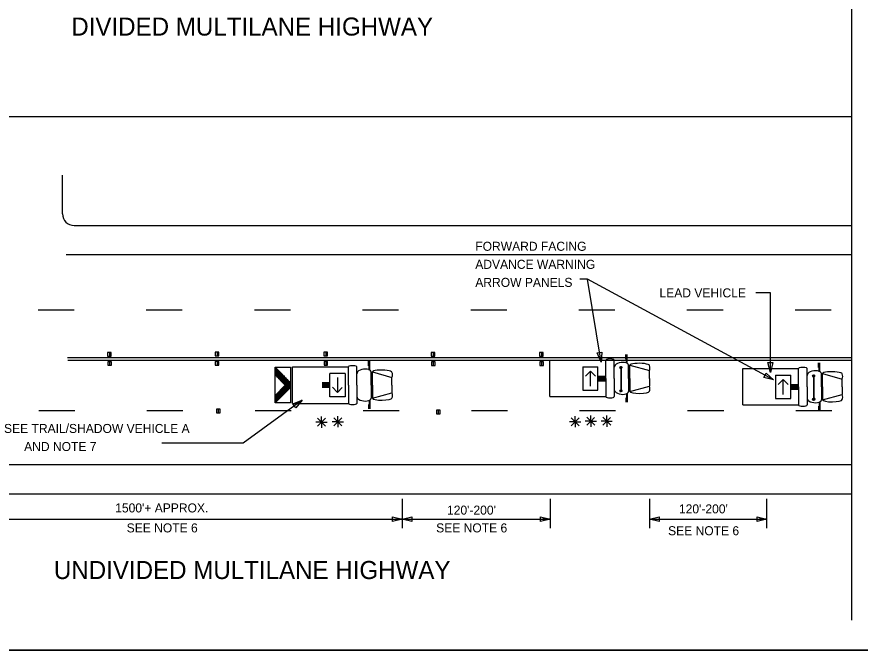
# Model space of a CAD drawing. Extents: x 1416408 to 1429341, y 372694 to 383211.
# Drawn here: x 1426733 to 1427672, y 372694 to 373399 of the extents above; entities that cross this region are included whole.
import ezdxf

# ---------------------------------------------------------------- set-up
doc = ezdxf.new("R2010")
doc.units = 0
for name, color, linetype in [('Default', 7, 'Continuous'), ('DSN_DRFT_Junk-No-Plot', 7, 'Continuous'), ('Level 1', 7, 'Continuous'), ('Working Level 1', 7, 'Continuous')]:
    doc.layers.add(name, color=color, linetype=linetype)

msp = doc.modelspace()

# ---------------------------------------------------------------- linework, layer by layer
at = {"layer": 'Default'}
for points in [[(1426234.86, 374479.9), (1426234.86, 372693.86), (1428995.11, 372693.86), (1428995.11, 374479.9)], [(1426234.86, 374479.9), (1426234.86, 372693.86), (1428995.11, 372693.86), (1428995.11, 374479.9)], [(1426234.86, 374479.9), (1428995.11, 374479.9), (1428995.11, 372693.86), (1426234.86, 372693.86)], [(1426234.86, 374479.9), (1426234.86, 372693.86), (1428995.11, 372693.86), (1428995.11, 374479.9)]]:
    msp.add_lwpolyline(points, close=True, dxfattribs=at)
at = {"layer": 'DSN_DRFT_Junk-No-Plot'}
msp.add_lwpolyline([(1426234.86, 374479.9), (1428995.11, 374479.9), (1428995.11, 372693.86), (1426234.86, 372693.86)], close=True, dxfattribs=at)
at = {"layer": 'Level 1'}
msp.add_lwpolyline([(1427050.38, 372972.19), (1426984.86, 372924.12), (1426893.95, 372924.12)], dxfattribs=at)
at = {"layer": 'Working Level 1'}
for p, q in [((1427662.56, 374447.3), (1427662.56, 372727.17)), ((1426337.99, 373287.72), (1427662, 373287.72)), ((1426783.42, 373179.42), (1426783.42, 373222.45)), ((1426796.27, 373166.43), (1427662.56, 373166.43)), ((1426787.3, 373134.22), (1427662.56, 373134.22)), ((1427575.65, 372994.53), (1427368.37, 373106.73)), ((1426788.93, 373019.55), (1427662.56, 373019.55)), ((1426833.63, 373025.14), (1426833.62, 373021.08)), ((1426833.62, 373021.08), (1426837.64, 373021.08)), ((1426837.64, 373025.14), (1426833.63, 373025.14)), ((1426835.65, 373025.14), (1426835.64, 373021.08)), ((1426837.64, 373021.08), (1426837.64, 373025.14)), ((1426953.6, 373025.45), (1426953.59, 373021.38)), ((1426953.59, 373021.38), (1426957.61, 373021.38)), ((1426957.61, 373025.45), (1426953.6, 373025.45)), ((1426955.62, 373025.45), (1426955.61, 373021.38)), ((1426957.61, 373021.38), (1426957.61, 373025.45)), ((1427074.65, 373025.31), (1427074.64, 373021.24)), ((1427074.64, 373021.24), (1427078.67, 373021.24)), ((1427078.67, 373025.31), (1427074.65, 373025.31)), ((1427076.66, 373025.31), (1427076.66, 373021.24)), ((1427078.67, 373021.24), (1427078.67, 373025.31)), ((1427194.34, 373025.08), (1427194.33, 373021.01)), ((1427194.33, 373021.01), (1427198.36, 373021.01)), ((1427198.36, 373025.08), (1427194.34, 373025.08)), ((1427196.35, 373025.08), (1427196.35, 373021.01)), ((1427198.36, 373021.01), (1427198.36, 373025.08)), ((1427314.97, 373025.08), (1427314.96, 373021.01)), ((1427314.96, 373021.01), (1427318.98, 373021.01)), ((1427318.98, 373025.08), (1427314.97, 373025.08)), ((1427316.99, 373025.08), (1427316.98, 373021.01)), ((1427318.98, 373021.01), (1427318.98, 373025.08)), ((1427411.05, 373017.86), (1427411.05, 373022.82)), ((1427411.83, 373013.07), (1427411.83, 373022.82)), ((1427412.49, 373013.07), (1427412.49, 373022.82)), ((1427476, 373019.55), (1427662.56, 373019.55)), ((1426789.49, 373016.73), (1427662.56, 373016.73)), ((1426833.81, 373014.91), (1426833.8, 373010.84)), ((1426833.8, 373010.84), (1426837.82, 373010.84)), ((1426837.82, 373014.91), (1426833.81, 373014.91)), ((1426835.83, 373014.91), (1426835.82, 373010.84)), ((1426837.82, 373010.84), (1426837.82, 373014.91)), ((1426953.65, 373015.1), (1426953.64, 373011.03)), ((1426953.64, 373011.03), (1426957.66, 373011.03)), ((1426957.66, 373015.1), (1426953.65, 373015.1)), ((1426955.66, 373015.1), (1426955.65, 373011.03)), ((1426957.66, 373011.03), (1426957.66, 373015.1)), ((1427074.83, 373014.98), (1427074.82, 373010.91)), ((1427074.82, 373010.91), (1427078.84, 373010.91)), ((1427078.84, 373014.98), (1427074.83, 373014.98)), ((1427076.85, 373014.98), (1427076.84, 373010.91)), ((1427078.84, 373010.91), (1427078.84, 373014.98)), ((1427124.25, 373010.34), (1427124.25, 373015.32)), ((1427125.02, 373005.56), (1427125.02, 373015.32)), ((1427125.68, 373005.56), (1427125.68, 373015.32)), ((1427194.52, 373014.75), (1427194.51, 373010.68)), ((1427194.51, 373010.68), (1427198.53, 373010.68)), ((1427198.53, 373014.75), (1427194.52, 373014.75)), ((1427196.54, 373014.75), (1427196.53, 373010.68)), ((1427198.53, 373010.68), (1427198.53, 373014.75)), ((1427315.15, 373014.75), (1427315.14, 373010.68)), ((1427315.14, 373010.68), (1427319.17, 373010.68)), ((1427319.17, 373014.75), (1427315.15, 373014.75)), ((1427317.16, 373014.75), (1427317.15, 373010.68)), ((1427319.17, 373010.68), (1427319.17, 373014.75)), ((1427326.51, 373016.64), (1427388.69, 373016.64)), ((1427326.51, 372976.02), (1427326.51, 373016.64)), ((1427388.69, 372996.33), (1427388.69, 373016.64)), ((1427398.21, 372996.33), (1427398.21, 373016.64)), ((1427414.17, 372996.33), (1427414.17, 373010.96)), ((1427415.5, 373010.96), (1427437.24, 373004.95)), ((1427415.5, 372996.33), (1427415.5, 373010.96)), ((1427625.84, 373008.52), (1427625.84, 373013.49)), ((1427626.62, 373003.73), (1427626.62, 373013.49)), ((1427627.28, 373003.73), (1427627.28, 373013.49)), ((1427020.31, 373008.83), (1427037.46, 372991.5)), ((1427039.69, 373009.13), (1427101.87, 373009.13)), ((1427039.69, 372968.52), (1427039.69, 373009.13)), ((1427098.23, 373001.82), (1427081.23, 373001.82)), ((1427081.23, 372975.82), (1427081.23, 373001.82)), ((1427098.23, 373001.82), (1427098.23, 372975.82)), ((1427101.87, 372988.83), (1427101.87, 373009.13)), ((1427111.4, 372988.83), (1427111.4, 373009.13)), ((1427127.36, 372988.83), (1427127.36, 373003.45)), ((1427128.68, 373003.45), (1427150.43, 372997.44)), ((1427128.68, 372988.83), (1427128.68, 373003.45)), ((1427363.03, 373009.34), (1427380.02, 373009.34)), ((1427363.03, 373009.34), (1427363.03, 372983.34)), ((1427371.53, 373004.37), (1427366.07, 372998.85)), ((1427371.53, 372987.74), (1427371.53, 373004.37)), ((1427371.53, 373004.37), (1427377.12, 372998.72)), ((1427380.02, 372983.34), (1427380.02, 373009.34)), ((1427404.28, 373008.68), (1427404.28, 373008.68)), ((1427405.3, 373008.1), (1427405.3, 372982.89)), ((1427405.37, 373008.1), (1427405.37, 372982.89)), ((1427405.45, 373008.1), (1427405.45, 372982.89)), ((1427405.58, 373008.1), (1427405.58, 372982.89)), ((1427405.74, 373009.53), (1427405.74, 373009.53)), ((1427405.77, 373008.1), (1427405.77, 372982.89)), ((1427437.24, 372996.33), (1427437.24, 373004.95)), ((1427541.29, 373007.3), (1427603.47, 373007.3)), ((1427541.29, 372966.69), (1427541.29, 373007.3)), ((1427603.47, 372987), (1427603.47, 373007.3)), ((1427613, 372987), (1427613, 373007.3)), ((1427628.96, 372987), (1427628.96, 373001.62)), ((1427630.29, 373001.62), (1427652.03, 372995.61)), ((1427630.29, 372987), (1427630.29, 373001.62)), ((1427020.31, 373000.16), (1427031.63, 372988.77)), ((1427081.23, 372991.41), (1427072.57, 372991.41)), ((1427089.73, 372997.41), (1427089.73, 372980.77)), ((1427150.43, 372988.83), (1427150.43, 372997.44)), ((1427380.02, 372998.93), (1427388.69, 372998.93)), ((1427380.02, 372997.63), (1427388.69, 372997.63)), ((1427380.02, 372996.33), (1427388.69, 372996.33)), ((1427380.02, 372995.04), (1427388.69, 372995.04)), ((1427380.02, 372993.74), (1427388.69, 372993.74)), ((1427388.69, 372996.33), (1427388.69, 372976.03)), ((1427398.21, 372996.33), (1427398.21, 372976.03)), ((1427414.17, 372996.33), (1427414.17, 372981.71)), ((1427415.5, 372996.33), (1427415.5, 372981.71)), ((1427437.24, 372996.33), (1427437.24, 372987.72)), ((1427577.82, 373000), (1427594.81, 373000)), ((1427577.82, 373000), (1427577.82, 372974)), ((1427586.31, 372995.03), (1427580.86, 372989.52)), ((1427586.31, 372978.41), (1427586.31, 372995.03)), ((1427586.31, 372995.03), (1427591.9, 372989.38)), ((1427594.81, 372974), (1427594.81, 373000)), ((1427619.07, 372999.35), (1427619.07, 372999.35)), ((1427620.09, 372998.76), (1427620.09, 372973.55)), ((1427620.16, 372998.76), (1427620.16, 372973.55)), ((1427620.23, 372998.76), (1427620.23, 372973.55)), ((1427620.37, 372998.76), (1427620.37, 372973.55)), ((1427620.52, 373000.19), (1427620.52, 373000.19)), ((1427620.56, 372998.76), (1427620.56, 372973.55)), ((1427652.03, 372987), (1427652.03, 372995.61)), ((1427020.31, 372977.34), (1427031.63, 372988.77)), ((1427020.41, 372969.01), (1427037.38, 372986.17)), ((1427081.23, 372990.12), (1427072.57, 372990.12)), ((1427081.23, 372988.82), (1427072.57, 372988.82)), ((1427081.23, 372987.52), (1427072.57, 372987.52)), ((1427081.23, 372986.21), (1427072.57, 372986.21)), ((1427089.73, 372980.77), (1427084.13, 372986.43)), ((1427089.73, 372980.77), (1427095.18, 372986.3)), ((1427101.87, 372988.83), (1427101.87, 372968.52)), ((1427111.4, 372988.83), (1427111.4, 372968.52)), ((1427127.36, 372988.83), (1427127.36, 372974.2)), ((1427128.68, 372988.83), (1427128.68, 372974.2)), ((1427150.43, 372988.83), (1427150.43, 372980.21)), ((1427363.03, 372983.34), (1427380.02, 372983.34)), ((1427404.35, 372982.67), (1427404.35, 372982.67)), ((1427405.8, 372983.52), (1427405.8, 372983.52)), ((1427415.5, 372981.71), (1427437.24, 372987.72)), ((1427594.81, 372989.59), (1427603.47, 372989.59)), ((1427594.81, 372988.29), (1427603.47, 372988.29)), ((1427594.81, 372987), (1427603.47, 372987)), ((1427594.81, 372985.7), (1427603.47, 372985.7)), ((1427594.81, 372984.4), (1427603.47, 372984.4)), ((1427603.47, 372987), (1427603.47, 372966.69)), ((1427613, 372987), (1427613, 372966.69)), ((1427628.96, 372987), (1427628.96, 372972.37)), ((1427630.29, 372987), (1427630.29, 372972.37)), ((1427652.03, 372987), (1427652.03, 372978.38)), ((1427098.23, 372975.82), (1427081.23, 372975.82)), ((1427128.68, 372974.2), (1427150.43, 372980.21)), ((1427326.51, 372976.03), (1427388.69, 372976.03)), ((1427411.05, 372974.82), (1427411.05, 372969.85)), ((1427411.83, 372979.6), (1427411.83, 372969.85)), ((1427412.49, 372979.6), (1427412.49, 372969.85)), ((1427577.82, 372974), (1427594.81, 372974)), ((1427619.14, 372973.33), (1427619.14, 372973.33)), ((1427620.59, 372974.19), (1427620.59, 372974.19)), ((1427630.29, 372972.37), (1427652.03, 372978.38)), ((1427039.69, 372968.52), (1427101.87, 372968.52)), ((1427124.25, 372967.3), (1427124.25, 372962.34)), ((1427125.02, 372972.09), (1427125.02, 372962.34)), ((1427125.68, 372972.09), (1427125.68, 372962.34)), ((1427541.29, 372966.69), (1427603.47, 372966.69)), ((1427625.84, 372965.48), (1427625.84, 372960.51)), ((1427626.62, 372970.26), (1427626.62, 372960.51)), ((1427627.28, 372970.26), (1427627.28, 372960.51)), ((1426959.02, 372961.96), (1426955, 372961.96)), ((1426955, 372961.96), (1426955, 372957.89)), ((1426955, 372957.89), (1426959.02, 372957.89)), ((1426957.02, 372961.96), (1426957.01, 372957.89)), ((1426959.02, 372957.89), (1426959.02, 372961.96)), ((1427071.96, 372947.73), (1427071.96, 372954.03)), ((1427090.15, 372948.13), (1427090.15, 372954.43)), ((1427204.03, 372961.01), (1427200.01, 372961.01)), ((1427200.01, 372961.01), (1427200.01, 372956.94)), ((1427200.01, 372956.94), (1427204.03, 372956.94)), ((1427202.03, 372961.01), (1427202.02, 372956.94)), ((1427204.03, 372956.94), (1427204.03, 372961.01)), ((1427354.59, 372948.13), (1427354.59, 372954.43)), ((1427371.98, 372948.53), (1427371.98, 372954.83)), ((1427389.77, 372948.53), (1427389.77, 372954.83)), ((1427071.96, 372947.73), (1427065.73, 372947.73)), ((1427071.96, 372947.73), (1427067.56, 372952.18)), ((1427071.96, 372947.73), (1427067.56, 372943.28)), ((1427071.86, 372947.65), (1427076.27, 372952.1)), ((1427071.96, 372947.73), (1427076.37, 372943.28)), ((1427071.96, 372947.73), (1427071.96, 372941.43)), ((1427071.96, 372947.73), (1427078.19, 372947.73)), ((1427090.15, 372948.13), (1427083.91, 372948.13)), ((1427090.15, 372948.13), (1427085.74, 372952.58)), ((1427090.15, 372948.13), (1427085.74, 372943.68)), ((1427090.04, 372948.05), (1427094.45, 372952.5)), ((1427090.15, 372948.13), (1427094.55, 372943.68)), ((1427090.15, 372948.13), (1427090.15, 372941.83)), ((1427090.15, 372948.13), (1427096.37, 372948.13)), ((1427354.59, 372948.13), (1427348.35, 372948.13)), ((1427354.59, 372948.13), (1427350.18, 372952.58)), ((1427354.59, 372948.13), (1427350.18, 372943.68)), ((1427354.48, 372948.05), (1427358.89, 372952.5)), ((1427354.59, 372948.13), (1427358.99, 372943.68)), ((1427354.59, 372948.13), (1427354.59, 372941.83)), ((1427354.59, 372948.13), (1427360.82, 372948.13)), ((1427371.98, 372948.53), (1427365.75, 372948.53)), ((1427371.98, 372948.53), (1427367.58, 372952.98)), ((1427371.98, 372948.53), (1427367.58, 372944.07)), ((1427371.87, 372948.45), (1427376.29, 372952.9)), ((1427371.98, 372948.53), (1427376.39, 372944.07)), ((1427371.98, 372948.53), (1427371.98, 372942.23)), ((1427371.98, 372948.53), (1427378.21, 372948.53)), ((1427389.77, 372948.53), (1427383.53, 372948.53)), ((1427389.77, 372948.53), (1427385.36, 372952.98)), ((1427389.77, 372948.53), (1427385.36, 372944.07)), ((1427389.66, 372948.45), (1427394.07, 372952.9)), ((1427389.77, 372948.53), (1427394.17, 372944.07)), ((1427389.77, 372948.53), (1427389.77, 372942.23)), ((1427389.77, 372948.53), (1427396, 372948.53)), ((1426337.56, 372900.37), (1427662.56, 372900.37)), ((1426337.56, 372867.91), (1427662.56, 372867.91)), ((1427161.87, 372862.09), (1427161.87, 372829.49)), ((1427326.56, 372862.09), (1427326.56, 372829.49)), ((1427437.3, 372862.09), (1427437.3, 372829.49)), ((1427567.96, 372862.09), (1427567.96, 372829.49)), ((1426636.93, 372839.64), (1427161.87, 372839.64)), ((1427161.87, 372839.64), (1427157.37, 372839.64)), ((1427161.87, 372839.64), (1427171, 372839.64)), ((1427161.87, 372839.64), (1427326.56, 372839.64)), ((1427437.3, 372839.64), (1427446.43, 372839.64)), ((1427437.3, 372839.64), (1427567.96, 372839.64))]:
    msp.add_line(p, q, dxfattribs=at)
for points in [[(1427383.73, 373014.45), (1427368.37, 373106.73), (1427359.77, 373106.73)], [(1427572.11, 373002.96), (1427572.11, 373091.49), (1427555.88, 373091.49)], [(1426756.23, 373072.7), (1426796.4, 373072.7)], [(1426876.72, 373072.7), (1426916.89, 373072.7)], [(1426997.21, 373072.7), (1427037.38, 373072.7)], [(1427117.7, 373072.7), (1427157.87, 373072.7)], [(1427238.2, 373072.7), (1427278.37, 373072.7)], [(1427358.69, 373072.7), (1427398.86, 373072.7)], [(1427479.18, 373072.7), (1427519.35, 373072.7)], [(1427599.67, 373072.7), (1427639.84, 373072.7)], [(1427020.31, 373007.9), (1427030.72, 372989.66)], [(1427020.31, 373006.33), (1427028.67, 372991.68)], [(1427020.31, 373004.76), (1427026.6, 372993.73)], [(1427020.31, 373003.19), (1427024.54, 372995.77)], [(1427020.31, 373001.61), (1427022.48, 372997.82)], [(1427021.18, 373007.95), (1427034.98, 372983.77)], [(1427023.3, 373005.8), (1427035.55, 372984.34)], [(1427025.42, 373003.67), (1427036.12, 372984.92)], [(1427027.54, 373001.53), (1427036.69, 372985.49)], [(1427404.24, 373008.24), (1427404.68, 373007.48)], [(1427404.28, 373008.68), (1427405.08, 373007.26)], [(1427404.38, 373008.98), (1427405.4, 373007.2)], [(1427404.53, 373009.21), (1427405.66, 373007.23)], [(1427404.71, 373009.38), (1427405.9, 373007.3)], [(1427404.91, 373009.52), (1427406.11, 373007.41)], [(1427405.15, 373009.59), (1427406.29, 373007.58)], [(1427405.4, 373009.65), (1427406.46, 373007.79)], [(1427405.7, 373009.6), (1427406.57, 373008.06)], [(1427406.05, 373009.47), (1427406.64, 373008.45)], [(1427020.31, 373000.04), (1427020.41, 372999.87)], [(1427029.65, 372999.39), (1427037.27, 372986.06)], [(1427031.77, 372997.25), (1427037.4, 372987.39)], [(1427033.89, 372995.11), (1427037.42, 372988.93)], [(1427036, 372992.98), (1427037.45, 372990.44)], [(1427619.03, 372998.9), (1427619.47, 372998.14)], [(1427619.07, 372999.35), (1427619.87, 372997.92)], [(1427619.16, 372999.65), (1427620.18, 372997.86)], [(1427619.31, 372999.87), (1427620.45, 372997.89)], [(1427619.5, 373000.04), (1427620.69, 372997.96)], [(1427619.69, 373000.18), (1427620.9, 372998.07)], [(1427619.93, 373000.25), (1427621.08, 372998.24)], [(1427620.18, 373000.31), (1427621.24, 372998.45)], [(1427620.49, 373000.27), (1427621.36, 372998.73)], [(1427620.84, 373000.13), (1427621.43, 372999.11)], [(1427025.13, 372982.2), (1427028.16, 372976.9)], [(1427025.69, 372982.78), (1427028.72, 372977.47)], [(1427026.26, 372983.36), (1427029.29, 372978.04)], [(1427026.82, 372983.93), (1427029.85, 372978.61)], [(1427027.39, 372984.51), (1427030.43, 372979.18)], [(1427027.96, 372985.08), (1427031, 372979.76)], [(1427028.53, 372985.64), (1427031.57, 372980.33)], [(1427029.09, 372986.22), (1427032.14, 372980.91)], [(1427029.66, 372986.8), (1427032.71, 372981.48)], [(1427030.24, 372987.37), (1427033.27, 372982.05)], [(1427030.81, 372987.95), (1427033.85, 372982.63)], [(1427031.38, 372988.52), (1427034.42, 372983.19)], [(1427404.32, 372982.24), (1427404.76, 372981.47)], [(1427404.35, 372982.67), (1427405.16, 372981.26)], [(1427404.45, 372982.98), (1427405.46, 372981.2)], [(1427404.6, 372983.21), (1427405.73, 372981.22)], [(1427404.77, 372983.37), (1427405.97, 372981.3)], [(1427404.97, 372983.51), (1427406.18, 372981.41)], [(1427405.21, 372983.58), (1427406.36, 372981.57)], [(1427405.46, 372983.63), (1427406.52, 372981.78)], [(1427405.77, 372983.6), (1427406.65, 372982.05)], [(1427406.12, 372983.47), (1427406.7, 372982.44)], [(1427020.31, 372976.5), (1427023.03, 372971.74)], [(1427020.31, 372974.93), (1427022.46, 372971.17)], [(1427020.31, 372973.35), (1427021.89, 372970.59)], [(1427020.57, 372977.61), (1427023.59, 372972.32)], [(1427021.14, 372978.19), (1427024.17, 372972.89)], [(1427021.71, 372978.75), (1427024.73, 372973.46)], [(1427022.29, 372979.34), (1427025.31, 372974.02)], [(1427022.84, 372979.91), (1427025.87, 372974.61)], [(1427023.41, 372980.48), (1427026.44, 372975.17)], [(1427023.97, 372981.05), (1427027.01, 372975.75)], [(1427024.55, 372981.63), (1427027.59, 372976.33)], [(1427619.11, 372972.9), (1427619.55, 372972.13)], [(1427619.14, 372973.33), (1427619.94, 372971.92)], [(1427619.24, 372973.64), (1427620.25, 372971.86)], [(1427619.39, 372973.87), (1427620.51, 372971.89)], [(1427619.56, 372974.04), (1427620.75, 372971.96)], [(1427619.76, 372974.17), (1427620.97, 372972.07)], [(1427620, 372974.24), (1427621.15, 372972.23)], [(1427620.25, 372974.3), (1427621.31, 372972.45)], [(1427620.56, 372974.26), (1427621.43, 372972.71)], [(1427620.91, 372974.13), (1427621.49, 372973.1)], [(1427020.31, 372971.79), (1427021.32, 372970.01)], [(1427020.31, 372970.22), (1427020.75, 372969.45)], [(1426756.95, 372960.54), (1426797.12, 372960.54)], [(1426877.44, 372960.54), (1426917.61, 372960.54)], [(1426997.93, 372960.54), (1427038.1, 372960.54)], [(1427118.42, 372960.54), (1427158.59, 372960.54)], [(1427238.92, 372960.54), (1427279.09, 372960.54)], [(1427359.41, 372960.54), (1427399.58, 372960.54)], [(1427479.9, 372960.54), (1427520.07, 372960.54)], [(1427600.4, 372960.54), (1427640.56, 372960.54)], [(1427326.56, 372839.64), (1427318.25, 372839.64), (1427318.25, 372839.05)], [(1427567.96, 372839.64), (1427559.64, 372839.64), (1427559.64, 372839.05)]]:
    msp.add_lwpolyline(points, dxfattribs=at)
for points in [[(1427384.24, 373025.66), (1427383.73, 373014.45), (1427378.96, 373024.58)], [(1427574.8, 373013.84), (1427572.11, 373002.96), (1427569.42, 373013.84)], [(1427037.51, 372969.01), (1427020.31, 372969.01), (1427020.31, 373008.83), (1427037.51, 373008.83)], [(1427567.43, 373002.06), (1427575.65, 372994.53), (1427564.89, 372997.26)], [(1427040.09, 372968), (1427050.38, 372972.19), (1427043.25, 372963.6)], [(1427151.11, 372842.37), (1427161.87, 372839.64), (1427151.11, 372836.92)], [(1427172.64, 372836.92), (1427161.87, 372839.64), (1427172.64, 372842.37)], [(1427315.8, 372842.37), (1427326.56, 372839.64), (1427315.8, 372836.92)], [(1427448.07, 372836.92), (1427437.3, 372839.64), (1427448.07, 372842.37)], [(1427557.2, 372842.37), (1427567.96, 372839.64), (1427557.2, 372836.92)]]:
    msp.add_lwpolyline(points, close=True, dxfattribs=at)
for centre, major_axis, ratio, start_param, end_param in [((1426796.27, 373179.42), (0, -12.99), 0.989089, 4.712389, 6.283185), ((1427106.64, 373009.13), (4.76, 0), 0.27289, 6.283185, 9.424778), ((1427393.45, 373016.64), (4.76, 0), 0.27289, 6.283185, 9.424778), ((1427406.19, 373009.96), (7.98, 1.01), 0.50847, 6.28135, 9.422943), ((1427426.37, 373010.83), (10.87, -0.13), 0.205643, 0.000054, 3.141647), ((1427431.92, 373007.83), (0, 6.1), 0.989089, 4.221603, 5.203174), ((1427119.38, 373002.45), (7.98, 1.01), 0.50847, 6.28135, 9.422943), ((1427139.56, 373003.32), (10.87, -0.13), 0.205643, 0.000054, 3.141647), ((1427145.11, 373000.31), (0, 6.1), 0.989089, 4.221603, 5.203174), ((1427608.23, 373007.3), (4.76, 0), 0.27289, 6.283185, 9.424778), ((1427620.98, 373000.62), (7.98, 1.01), 0.50847, 6.28135, 9.422943), ((1427641.16, 373001.5), (10.87, -0.13), 0.205643, 0.000054, 3.141647), ((1427646.71, 372998.49), (0, 6.1), 0.989089, 4.221603, 5.203174), ((1427406.19, 372982.71), (7.98, -1.01), 0.50847, 3.143427, 6.28502), ((1427426.37, 372981.83), (10.87, 0.13), 0.205643, 3.141539, 6.283131), ((1427431.92, 372984.84), (0, 6.1), 0.989089, 4.221604, 5.203174), ((1427119.38, 372975.2), (7.98, -1.01), 0.50847, 3.143427, 6.28502), ((1427139.56, 372974.32), (10.87, 0.13), 0.205643, 3.141539, 6.283131), ((1427145.11, 372977.33), (0, 6.1), 0.989089, 4.221604, 5.203174), ((1427393.45, 372976.03), (4.76, 0), 0.27289, 3.141593, 6.283185), ((1427620.98, 372973.37), (7.98, -1.01), 0.50847, 3.143427, 6.28502), ((1427641.16, 372972.5), (10.87, 0.13), 0.205643, 3.141539, 6.283131), ((1427646.71, 372975.51), (0, 6.1), 0.989089, 4.221604, 5.203174), ((1427106.64, 372968.52), (4.76, 0), 0.27289, 3.141593, 6.283185), ((1427608.23, 372966.7), (4.76, 0), 0.27289, 3.141593, 6.283185)]:
    msp.add_ellipse(centre, major_axis=major_axis, ratio=ratio, start_param=start_param, end_param=end_param, dxfattribs=at)
for centre in [(1427405.43, 373008.42), (1427620.22, 372999.09), (1427405.5, 372982.42), (1427620.29, 372973.08)]:
    msp.add_ellipse(centre, major_axis=(0, -1.22), ratio=0.989089, dxfattribs=at)

# ---------------------------------------------------------------- texts
for s, p in [('DIVIDED MULTILANE HIGHWAY', (1426793.18, 373377.86)), ('UNDIVIDED MULTILANE HIGHWAY', (1426773.81, 372772.98))]:
    msp.add_text(s, height=20.0929, rotation=0, dxfattribs=at).set_placement(p)
for s, height, p in [('FORWARD FACING', 10.0465, (1427243.33, 373138.32)), ('ADVANCE WARNING ', 10.0465, (1427243.33, 373118.23)), ('ARROW PANELS', 10.0465, (1427243.33, 373098.14)), ('LEAD VEHICLE', 10.0465, (1427448.55, 373086.46)), ('SEE TRAIL/SHADOW VEHICLE A', 10.0465, (1426718.25, 372935.55)), ('      AND NOTE 7', 10.0465, (1426718.25, 372915.46)), ("1500'+ APPROX.", 10.0465, (1426842.13, 372847.1)), ("120'-200'", 10.046, (1427211.83, 372844.65)), ("120'-200'", 10.046, (1427470.24, 372846.05)), ('SEE NOTE 6', 10.046, (1426854.92, 372824.87)), ('SEE NOTE 6', 10.046, (1427199.74, 372824.87)), ('SEE NOTE 6', 10.046, (1427458.15, 372821.73))]:
    msp.add_text(s, height=height, dxfattribs=at).set_placement(p)

doc.saveas('drawing.dxf')
